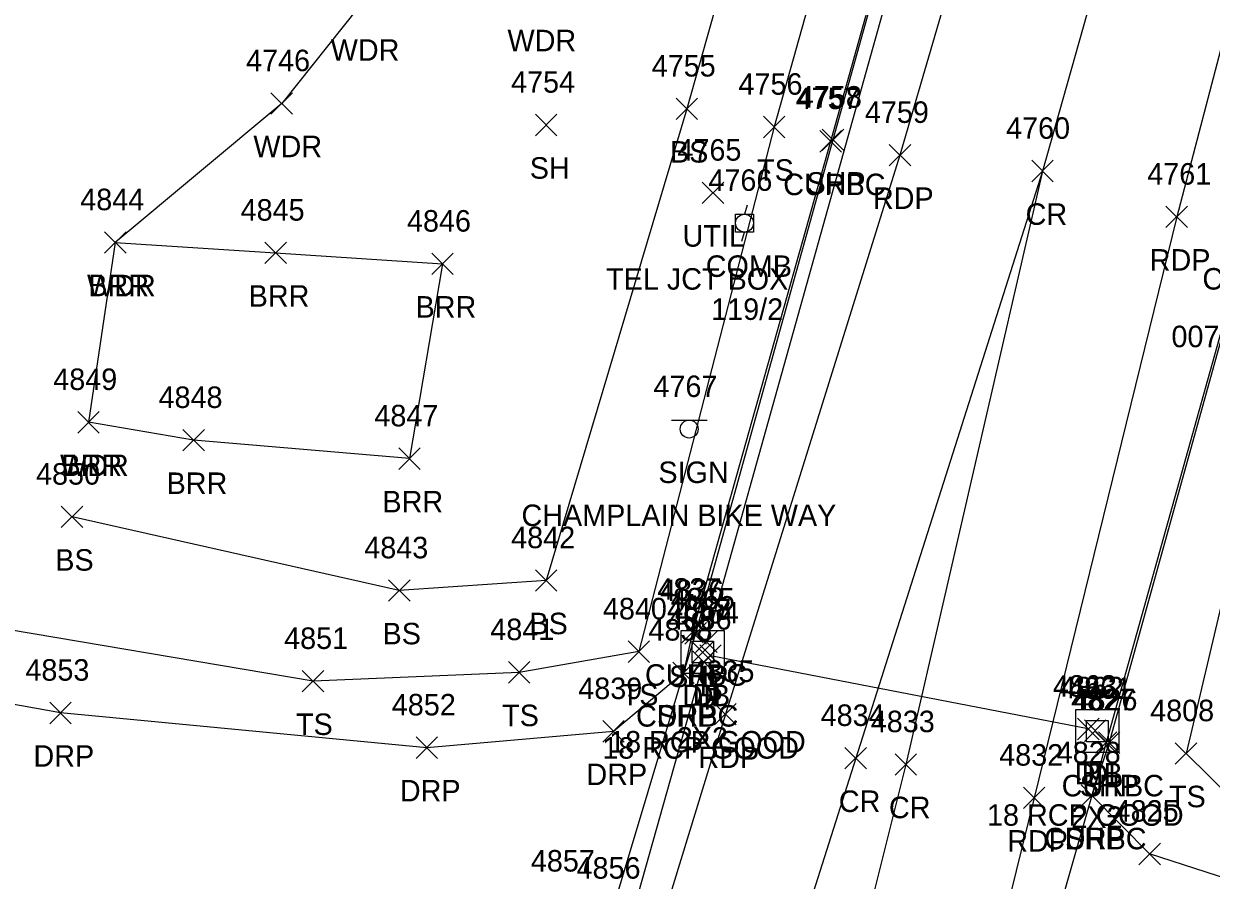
# Model space of a CAD drawing. Extents: x 1443912 to 1445411, y 621446 to 623693.
# Drawn here: x 1444769.4 to 1444879.8, y 622939.4 to 623019 of the extents above; entities that cross this region are included whole.
import ezdxf

# ---------------------------------------------------------------- set-up
doc = ezdxf.new("R2010")
doc.units = 0
for name, color, linetype in [('D_A', 7, 'Continuous'), ('D_C', 7, 'Continuous'), ('D_I', 7, 'Continuous'), ('D_TIC', 7, 'Continuous'), ('DCP', 7, 'Continuous'), ('DS', 7, 'Continuous'), ('L_A', 7, 'Continuous'), ('L_I', 7, 'Continuous'), ('L_TIC', 7, 'Continuous'), ('LABL', 7, 'Continuous'), ('LAWA', 7, 'Continuous'), ('LELB', 7, 'Continuous'), ('P_A', 7, 'Continuous'), ('P_I', 7, 'Continuous'), ('P_TIC', 7, 'Continuous'), ('PET', 7, 'Continuous'), ('PRC', 7, 'Continuous'), ('PSP', 7, 'Continuous'), ('R_A', 7, 'Continuous'), ('R_I', 7, 'Continuous'), ('R_TIC', 7, 'Continuous'), ('RC', 7, 'Continuous'), ('RDP', 7, 'Continuous'), ('S_A', 7, 'Continuous'), ('S_C', 7, 'Continuous'), ('S_I', 7, 'Continuous'), ('SSGN', 7, 'Continuous'), ('U_A', 7, 'Continuous'), ('U_C', 7, 'Continuous'), ('U_I', 7, 'Continuous'), ('UDEFAULT', 7, 'Continuous'), ('UP', 7, 'Continuous')]:
    doc.layers.add(name, color=color, linetype=linetype)

msp = doc.modelspace()

# ---------------------------------------------------------------- linework, layer by layer
at = {"layer": 'D_TIC'}
for points in [[(1444831.84, 622960.57), (1444833.84, 622962.57)], [(1444833.84, 622960.57), (1444831.84, 622962.57)], [(1444831.5, 622959.58), (1444833.5, 622961.58)], [(1444833.5, 622959.58), (1444831.5, 622961.58)], [(1444831.59, 622958.7), (1444833.59, 622960.7)], [(1444833.59, 622958.7), (1444831.59, 622960.7)], [(1444832.22, 622959.27), (1444834.22, 622961.27)], [(1444834.22, 622959.27), (1444832.22, 622961.27)], [(1444867.36, 622952.46), (1444869.36, 622954.46)], [(1444869.36, 622952.46), (1444867.36, 622954.46)], [(1444868, 622952.31), (1444870, 622954.31)], [(1444870, 622952.31), (1444868, 622954.31)]]:
    msp.add_lwpolyline(points, dxfattribs=at)
at = {"layer": 'DCP'}
for points in [[(1444882.45, 623138.81), (1444832.84, 622961.57)], [(1444832.59, 622959.7), (1444808.88, 622875.73)], [(1444868.36, 622953.46), (1444833.22, 622960.27)]]:
    msp.add_lwpolyline(points, dxfattribs=at)
at = {"layer": 'DS'}
for p, q in [((1444830.51, 622962.62), (1444834.51, 622962.62)), ((1444830.51, 622958.62), (1444830.51, 622962.62)), ((1444834.51, 622962.62), (1444834.51, 622958.62)), ((1444831.51, 622959.62), (1444831.51, 622961.62)), ((1444831.51, 622961.62), (1444833.51, 622961.62)), ((1444833.51, 622961.62), (1444833.51, 622959.62)), ((1444832.52, 622960.63), (1444832.52, 622960.63)), ((1444832.52, 622960.63), (1444832.52, 622960.63)), ((1444833.51, 622959.62), (1444831.51, 622959.62)), ((1444834.51, 622958.62), (1444830.51, 622958.62)), ((1444867.2, 622955.26), (1444871.2, 622955.26)), ((1444867.2, 622951.26), (1444867.2, 622955.26)), ((1444871.2, 622955.26), (1444871.2, 622951.26)), ((1444868.2, 622952.26), (1444868.2, 622954.26)), ((1444868.2, 622954.26), (1444870.2, 622954.26)), ((1444870.2, 622954.26), (1444870.2, 622952.26)), ((1444869.21, 622953.26), (1444869.21, 622953.26)), ((1444869.21, 622953.26), (1444869.21, 622953.26)), ((1444870.2, 622952.26), (1444868.2, 622952.26)), ((1444871.2, 622951.26), (1444867.2, 622951.26))]:
    msp.add_line(p, q, dxfattribs=at)
at = {"layer": 'L_TIC'}
for points in [[(1444792.35, 623010.63), (1444794.35, 623012.63)], [(1444794.35, 623010.63), (1444792.35, 623012.63)], [(1444830.02, 623010.13), (1444832.02, 623012.13)], [(1444832.02, 623010.13), (1444830.02, 623012.13)], [(1444816.94, 623008.63), (1444818.94, 623010.63)], [(1444818.94, 623008.63), (1444816.94, 623010.63)], [(1444838.15, 623008.44), (1444840.15, 623010.44)], [(1444840.15, 623008.44), (1444838.15, 623010.44)], [(1444776.88, 622997.7), (1444778.88, 622999.7)], [(1444778.88, 622997.7), (1444776.88, 622999.7)], [(1444776.88, 622997.7), (1444778.88, 622999.7)], [(1444778.88, 622997.7), (1444776.88, 622999.7)], [(1444791.79, 622996.73), (1444793.79, 622998.73)], [(1444793.79, 622996.73), (1444791.79, 622998.73)], [(1444807.31, 622995.71), (1444809.31, 622997.71)], [(1444809.31, 622995.71), (1444807.31, 622997.71)], [(1444774.38, 622980.98), (1444776.38, 622982.98)], [(1444776.38, 622980.98), (1444774.38, 622982.98)], [(1444774.38, 622980.98), (1444776.38, 622982.98)], [(1444776.38, 622980.98), (1444774.38, 622982.98)], [(1444784.16, 622979.31), (1444786.16, 622981.31)], [(1444786.16, 622979.31), (1444784.16, 622981.31)], [(1444804.23, 622977.6), (1444806.23, 622979.6)], [(1444806.23, 622977.6), (1444804.23, 622979.6)], [(1444772.86, 622972.18), (1444774.86, 622974.18)], [(1444774.86, 622972.18), (1444772.86, 622974.18)], [(1444816.95, 622966.27), (1444818.95, 622968.27)], [(1444818.95, 622966.27), (1444816.95, 622968.27)], [(1444803.29, 622965.33), (1444805.29, 622967.33)], [(1444805.29, 622965.33), (1444803.29, 622967.33)], [(1444825.56, 622959.65), (1444827.56, 622961.65)], [(1444827.56, 622959.65), (1444825.56, 622961.65)], [(1444814.44, 622957.72), (1444816.44, 622959.72)], [(1444816.44, 622957.72), (1444814.44, 622959.72)], [(1444795.27, 622956.9), (1444797.27, 622958.9)], [(1444797.27, 622956.9), (1444795.27, 622958.9)], [(1444876.45, 622950.18), (1444878.45, 622952.18)], [(1444878.45, 622950.18), (1444876.45, 622952.18)]]:
    msp.add_lwpolyline(points, dxfattribs=at)
at = {"layer": 'LABL'}
msp.add_lwpolyline([(1444777.88, 622998.7), (1444792.79, 622997.73), (1444808.31, 622996.71), (1444805.23, 622978.6), (1444785.16, 622980.31), (1444775.38, 622981.98)], dxfattribs=at)
at = {"layer": 'LAWA'}
msp.add_lwpolyline([(1444787.83, 623062.76), (1444810.01, 623056.94), (1444821.16, 623040.6), (1444816.99, 623021.48), (1444800.54, 623020.6), (1444793.35, 623011.63), (1444777.88, 622998.7), (1444775.38, 622981.98)], dxfattribs=at)
at = {"layer": 'LELB'}
for points in [[(1444965.39, 623126.71), (1444945.13, 623132.56), (1444929.57, 623133.35), (1444925.64, 623128.64), (1444923.13, 623120.2), (1444914.4, 623088.98), (1444907.7, 623062.92), (1444896.39, 623030.41), (1444888.48, 622997.96), (1444877.45, 622951.18), (1444886.07, 622942.7), (1444898.81, 622937.04), (1444925.54, 622926.46)], [(1444838.66, 623128.87), (1444862.71, 623115.01), (1444852.14, 623081.42), (1444841.44, 623048.05), (1444831.02, 623011.13), (1444817.95, 622967.27), (1444804.29, 622966.33), (1444773.86, 622973.18)], [(1444858.07, 623125.91), (1444865.13, 623121.84), (1444868.88, 623113.06), (1444860.27, 623080.32), (1444849.37, 623045.92), (1444839.15, 623009.44), (1444826.56, 622960.65), (1444815.44, 622958.72), (1444796.27, 622957.9), (1444763.62, 622963.41)]]:
    msp.add_lwpolyline(points, dxfattribs=at)
at = {"layer": 'P_TIC'}
for points in [[(1444843.61, 623007.24), (1444845.61, 623009.24)], [(1444845.61, 623007.24), (1444843.61, 623009.24)], [(1444849.84, 623005.82), (1444851.84, 623007.82)], [(1444851.84, 623005.82), (1444849.84, 623007.82)], [(1444863.1, 623004.34), (1444865.1, 623006.34)], [(1444865.1, 623004.34), (1444863.1, 623006.34)], [(1444863.1, 623004.34), (1444865.1, 623006.34)], [(1444865.1, 623004.34), (1444863.1, 623006.34)], [(1444875.58, 623000.08), (1444877.58, 623002.08)], [(1444877.58, 623000.08), (1444875.58, 623002.08)], [(1444830.84, 622961.35), (1444832.84, 622963.35)], [(1444832.84, 622961.35), (1444830.84, 622963.35)], [(1444829.72, 622957.68), (1444831.72, 622959.68)], [(1444831.72, 622957.68), (1444829.72, 622959.68)], [(1444833.61, 622953.83), (1444835.61, 622955.83)], [(1444835.61, 622953.83), (1444833.61, 622955.83)], [(1444869.02, 622951.2), (1444871.02, 622953.2)], [(1444871.02, 622951.2), (1444869.02, 622953.2)], [(1444845.73, 622949.74), (1444847.73, 622951.74)], [(1444847.73, 622949.74), (1444845.73, 622951.74)], [(1444850.39, 622949.16), (1444852.39, 622951.16)], [(1444852.39, 622949.16), (1444850.39, 622951.16)], [(1444867.68, 622946.27), (1444869.68, 622948.27)], [(1444869.68, 622946.27), (1444867.68, 622948.27)], [(1444862.33, 622946.05), (1444864.33, 622948.05)], [(1444864.33, 622946.05), (1444862.33, 622948.05)]]:
    msp.add_lwpolyline(points, dxfattribs=at)
at = {"layer": 'PET'}
for points in [[(1445036.7, 623677.7), (1445026.38, 623639.78), (1445008.65, 623576.15), (1444996.95, 623532.89), (1444979.78, 623472.47), (1444964.83, 623416.22), (1444955.71, 623382.54), (1444949.17, 623358.13), (1444939.29, 623323.43), (1444926.27, 623275.91), (1444914.83, 623235.04), (1444901.53, 623186.46), (1444892.14, 623152.69), (1444883.14, 623119.13), (1444870.13, 623073.23), (1444861.49, 623043.31), (1444850.84, 623006.82), (1444834.61, 622954.83), (1444817.28, 622898.33)], [(1445060.04, 623670.52), (1445049.49, 623631.42), (1445031.61, 623567.44), (1445020.44, 623527.05), (1445003.5, 623465.59), (1444988.1, 623409.14), (1444976.63, 623367.03), (1444962.49, 623315.05), (1444949.49, 623267.35), (1444937.78, 623225.39), (1444926.09, 623182.22), (1444915.48, 623145.05), (1444906.98, 623113.48), (1444893.64, 623066.1), (1444886.06, 623037.31), (1444876.58, 623001.08), (1444863.33, 622947.05), (1444849.43, 622890.74)]]:
    msp.add_lwpolyline(points, dxfattribs=at)
at = {"layer": 'PRC'}
for points in [[(1445048.12, 623674.07), (1445038.05, 623635.88), (1445020.14, 623572.7), (1445008.5, 623529.11), (1444991.68, 623469.75), (1444976.21, 623412.44), (1444964.87, 623369.69), (1444950.64, 623318.47), (1444938.05, 623272.58), (1444925.39, 623227.3), (1444913.85, 623184.57), (1444903.74, 623148.67), (1444894.97, 623116.18), (1444881.8, 623068.92), (1444873.97, 623040.25), (1444864.1, 623005.34), (1444846.73, 622950.74), (1444829.37, 622896.11)], [(1444864.1, 623005.34), (1444851.39, 622950.16), (1444837.25, 622893.61), (1444822.84, 622838.02), (1444810.34, 622792.94), (1444799.32, 622750.35), (1444788.05, 622712.65), (1444779.51, 622680.27), (1444771.55, 622651.63), (1444762.01, 622615.65), (1444752.75, 622584.12), (1444739.92, 622538.84), (1444733.6, 622516.91), (1444722.13, 622475.76), (1444713.59, 622446.41), (1444702.09, 622404.55), (1444689.87, 622361.08), (1444676.17, 622311.92), (1444657.59, 622249.98), (1444643.66, 622204.01), (1444635.38, 622177.66), (1444620.59, 622126.88), (1444604.97, 622075.74)]]:
    msp.add_lwpolyline(points, dxfattribs=at)
at = {"layer": 'PSP'}
for points in [[(1444984.52, 623364.95), (1444970.17, 623313), (1444960.84, 623279.61), (1444959.91, 623275.87), (1444955.54, 623257.94), (1444945.5, 623223.6), (1444933.94, 623181.42), (1444927.82, 623159.66), (1444926.96, 623156.44), (1444922.1, 623137.71), (1444921.08, 623134.92), (1444914.5, 623111.78), (1444901.39, 623063.86), (1444892.12, 623031.22), (1444883.17, 622999.19), (1444870.02, 622952.2), (1444868.68, 622947.27), (1444864.21, 622931.67)], [(1444864.33, 623079.14), (1444854.72, 623044.47), (1444844.61, 623008.24), (1444831.84, 622962.35), (1444830.72, 622958.68), (1444824.08, 622936.54)]]:
    msp.add_lwpolyline(points, dxfattribs=at)
at = {"layer": 'R_TIC'}
for points in [[(1444843.4, 623007.1), (1444845.4, 623009.1)], [(1444845.4, 623007.1), (1444843.4, 623009.1)], [(1444830.55, 622961.48), (1444832.55, 622963.48)], [(1444832.55, 622961.48), (1444830.55, 622963.48)], [(1444829.72, 622957.68), (1444831.72, 622959.68)], [(1444831.72, 622957.68), (1444829.72, 622959.68)], [(1444829.72, 622957.68), (1444831.72, 622959.68)], [(1444831.72, 622957.68), (1444829.72, 622959.68)], [(1444771.78, 622953.95), (1444773.78, 622955.95)], [(1444773.78, 622953.95), (1444771.78, 622955.95)], [(1444823.2, 622952.24), (1444825.2, 622954.24)], [(1444825.2, 622952.24), (1444823.2, 622954.24)], [(1444805.85, 622950.72), (1444807.85, 622952.72)], [(1444807.85, 622950.72), (1444805.85, 622952.72)], [(1444869.3, 622951.19), (1444871.3, 622953.19)], [(1444871.3, 622951.19), (1444869.3, 622953.19)], [(1444867.68, 622946.27), (1444869.68, 622948.27)], [(1444869.68, 622946.27), (1444867.68, 622948.27)], [(1444867.68, 622946.27), (1444869.68, 622948.27)], [(1444869.68, 622946.27), (1444867.68, 622948.27)], [(1444873.06, 622940.84), (1444875.06, 622942.84)], [(1444875.06, 622940.84), (1444873.06, 622942.84)]]:
    msp.add_lwpolyline(points, dxfattribs=at)
at = {"layer": 'RC'}
for points in [[(1444922.1, 623137.71), (1444921.21, 623134.74), (1444914.79, 623111.77), (1444901.49, 623063.72), (1444892.45, 623031.11), (1444883.39, 622999.32), (1444870.3, 622952.19), (1444868.68, 622947.27)], [(1444874.86, 623117.34), (1444873.93, 623114.41), (1444864.15, 623079.21), (1444854.57, 623044.55), (1444844.4, 623008.1), (1444831.55, 622962.48), (1444830.72, 622958.68)]]:
    msp.add_lwpolyline(points, dxfattribs=at)
at = {"layer": 'RDP'}
for points in [[(1444830.72, 622958.68), (1444824.2, 622953.24), (1444806.85, 622951.72), (1444772.78, 622954.95), (1444760.33, 622957.18)], [(1444889.76, 622936.78), (1444874.06, 622941.84), (1444868.68, 622947.27)]]:
    msp.add_lwpolyline(points, dxfattribs=at)
at = {"layer": 'SSGN'}
for p, q in [((1444829.6, 622982.18), (1444832.93, 622982.18)), ((1444831.24, 622981.35), (1444831.24, 622981.35))]:
    msp.add_line(p, q, dxfattribs=at)
msp.add_circle((1444831.24, 622981.35), 0.833, dxfattribs=at)
at = {"layer": 'UDEFAULT'}
for points in [[(1444832.46, 623002.31), (1444834.46, 623004.31)], [(1444834.46, 623002.31), (1444832.46, 623004.31)]]:
    msp.add_lwpolyline(points, dxfattribs=at)
at = {"layer": 'UP'}
for p, q in [((1444835.56, 622999.66), (1444835.56, 623001.33)), ((1444835.56, 623001.33), (1444837.23, 623001.33)), ((1444836.64, 623002.16), (1444836.39, 623001.33)), ((1444837.23, 623001.33), (1444837.23, 622999.66)), ((1444836.39, 623000.5), (1444836.39, 623000.5)), ((1444837.23, 622999.66), (1444835.56, 622999.66)), ((1444836.14, 622998.83), (1444836.39, 622999.66))]:
    msp.add_line(p, q, dxfattribs=at)
msp.add_circle((1444836.39, 623000.5), 0.833, dxfattribs=at)

# ---------------------------------------------------------------- texts
at = {"layer": 'D_A'}
for s, p in [('P', (1444832.22, 622956.57)), ('DIB', (1444830.6, 622955.58)), ('DI', (1444831.57, 622955.63)), ('P', (1444832.6, 622955.27)), ('P', (1444831.97, 622954.7)), ('P', (1444867.74, 622948.46)), ('DIB', (1444867.1, 622948.31)), ('DI', (1444868.26, 622948.26))]:
    msp.add_text(s, height=2, dxfattribs=at).set_placement(p)
at = {"layer": 'D_C'}
for s, p in [('2X2', (1444830.09, 622951.63)), ('18 RCP GOOD', (1444823.17, 622950.7)), ('18 RCP GOOD', (1444823.8, 622951.27)), ('18 RCP GOOD', (1444858.94, 622944.46)), ('2X2', (1444866.78, 622944.26))]:
    msp.add_text(s, height=2, dxfattribs=at).set_placement(p)
at = {"layer": 'D_I'}
for s, p in [('4865', (1444829.53, 622964.57)), ('4867', (1444829.19, 622963.58)), ('4868', (1444829.21, 622963.63)), ('4866', (1444829.23, 622962.7)), ('4864', (1444829.92, 622963.27)), ('4863', (1444865.06, 622956.46)), ('4862', (1444865.7, 622956.31)), ('4861', (1444866.47, 622956.26))]:
    msp.add_text(s, height=2, dxfattribs=at).set_placement(p)
at = {"layer": 'L_A'}
for s, p in [('WDR', (1444814.35, 623016.48)), ('WDR', (1444797.91, 623015.6)), ('WDR', (1444790.72, 623006.63)), ('BS', (1444829.46, 623006.13)), ('SH', (1444816.42, 623004.63)), ('TS', (1444837.56, 623004.44)), ('WDR', (1444775.25, 622993.7)), ('BRR', (1444775.37, 622993.7)), ('BRR', (1444790.28, 622992.73)), ('BRR', (1444805.8, 622991.71)), ('WDR', (1444772.74, 622976.98)), ('BRR', (1444772.87, 622976.98)), ('BRR', (1444782.65, 622975.31)), ('BRR', (1444802.72, 622973.6)), ('BS', (1444772.3, 622968.18)), ('BS', (1444816.39, 622962.27)), ('BS', (1444802.73, 622961.33)), ('TS', (1444824.97, 622955.65)), ('TS', (1444794.68, 622952.9)), ('TS', (1444813.85, 622953.72)), ('TS', (1444875.86, 622946.18))]:
    msp.add_text(s, height=2, dxfattribs=at).set_placement(p)
at = {"layer": 'L_I'}
for s, p in [('4746', (1444790.04, 623014.63)), ('4755', (1444827.76, 623014.13)), ('4754', (1444814.68, 623012.63)), ('4756', (1444835.83, 623012.44)), ('4844', (1444774.62, 623001.7)), ('4844', (1444774.62, 623001.7)), ('4845', (1444789.53, 623000.73)), ('4846', (1444805, 622999.71)), ('4849', (1444772.11, 622984.98)), ('4849', (1444772.11, 622984.98)), ('4848', (1444781.9, 622983.31)), ('4847', (1444801.97, 622981.6)), ('4850', (1444770.51, 622976.18)), ('4843', (1444801.03, 622969.33)), ('4842', (1444814.69, 622970.27)), ('4840', (1444823.22, 622963.65)), ('4841', (1444812.75, 622961.72)), ('4851', (1444793.58, 622960.9)), ('4808', (1444874.11, 622954.18))]:
    msp.add_text(s, height=2, dxfattribs=at).set_placement(p)
at = {"layer": 'P_A'}
for s, p in [('SHP', (1444842.15, 623003.24)), ('RDP', (1444848.33, 623001.82)), ('CR', (1444862.53, 623000.34)), ('CR', (1444862.53, 623000.34)), ('RDP', (1444874.07, 622996.08)), ('SHP', (1444829.38, 622957.35)), ('SHP', (1444828.25, 622953.68)), ('RDP', (1444832.1, 622949.83)), ('SHP', (1444867.56, 622947.2)), ('CR', (1444845.16, 622945.74)), ('CR', (1444849.82, 622945.16)), ('RDP', (1444860.82, 622942.05)), ('SHP', (1444866.21, 622942.27))]:
    msp.add_text(s, height=2, dxfattribs=at).set_placement(p)
at = {"layer": 'P_I'}
for s, p in [('4758', (1444841.35, 623011.24)), ('4759', (1444847.58, 623009.82)), ('4760', (1444860.71, 623008.34)), ('4760', (1444860.71, 623008.34)), ('4761', (1444873.84, 623004.08)), ('4836', (1444828.53, 622965.35)), ('4838', (1444827.46, 622961.68)), ('4835', (1444831.36, 622957.83)), ('4827', (1444866.76, 622955.2)), ('4834', (1444843.47, 622953.74)), ('4833', (1444848.13, 622953.16)), ('4832', (1444860.07, 622950.05)), ('4828', (1444865.42, 622950.27)), ('4857', (1444816.52, 622940.2)), ('4856', (1444820.77, 622939.54)), ('4856', (1444820.77, 622939.54))]:
    msp.add_text(s, height=2, dxfattribs=at).set_placement(p)
at = {"layer": 'R_A'}
for s, p in [('CURBC', (1444839.99, 623003.1)), ('CURBC', (1444878.97, 622994.32)), ('CURBC', (1444827.13, 622957.48)), ('CURBC', (1444826.3, 622953.68)), ('DRP', (1444828.21, 622953.68)), ('DRP', (1444770.27, 622949.95)), ('DRP', (1444821.69, 622948.24)), ('DRP', (1444804.34, 622946.72)), ('CURBC', (1444865.88, 622947.19)), ('CURBC', (1444864.26, 622942.27)), ('DRP', (1444866.16, 622942.27))]:
    msp.add_text(s, height=2, dxfattribs=at).set_placement(p)
at = {"layer": 'R_I'}
for s, p in [('4757', (1444841.14, 623011.1)), ('4837', (1444828.29, 622965.48)), ('4838', (1444827.46, 622961.68)), ('4838', (1444827.46, 622961.68)), ('4853', (1444769.52, 622957.95)), ('4839', (1444820.93, 622956.24)), ('4826', (1444866.98, 622955.19)), ('4852', (1444803.59, 622954.72)), ('4828', (1444865.42, 622950.27)), ('4828', (1444865.42, 622950.27)), ('4825', (1444870.8, 622944.84))]:
    msp.add_text(s, height=2, dxfattribs=at).set_placement(p)
at = {"layer": 'S_A'}
msp.add_text('SIGN', height=2, dxfattribs=at).set_placement((1444828.38, 622976.33))
at = {"layer": 'S_C'}
for s, p in [('0070/0105/0320', (1444876.09, 622988.96)), ('CHAMPLAIN BIKE WAY', (1444815.65, 622972.33))]:
    msp.add_text(s, height=2, dxfattribs=at).set_placement(p)
at = {"layer": 'S_I'}
msp.add_text('4767', height=2, dxfattribs=at).set_placement((1444827.92, 622984.33))
at = {"layer": 'U_A'}
for s, p in [('UTIL', (1444830.63, 622998.31)), ('COMB', (1444832.78, 622995.5))]:
    msp.add_text(s, height=2, dxfattribs=at).set_placement(p)
at = {"layer": 'U_C'}
for s, p in [('TEL JCT BOX', (1444823.52, 622994.31)), ('119/2', (1444833.29, 622991.5))]:
    msp.add_text(s, height=2, dxfattribs=at).set_placement(p)
at = {"layer": 'U_I'}
for s, p in [('4765', (1444830.15, 623006.31)), ('4766', (1444833.03, 623003.5))]:
    msp.add_text(s, height=2, dxfattribs=at).set_placement(p)

doc.saveas('drawing.dxf')
